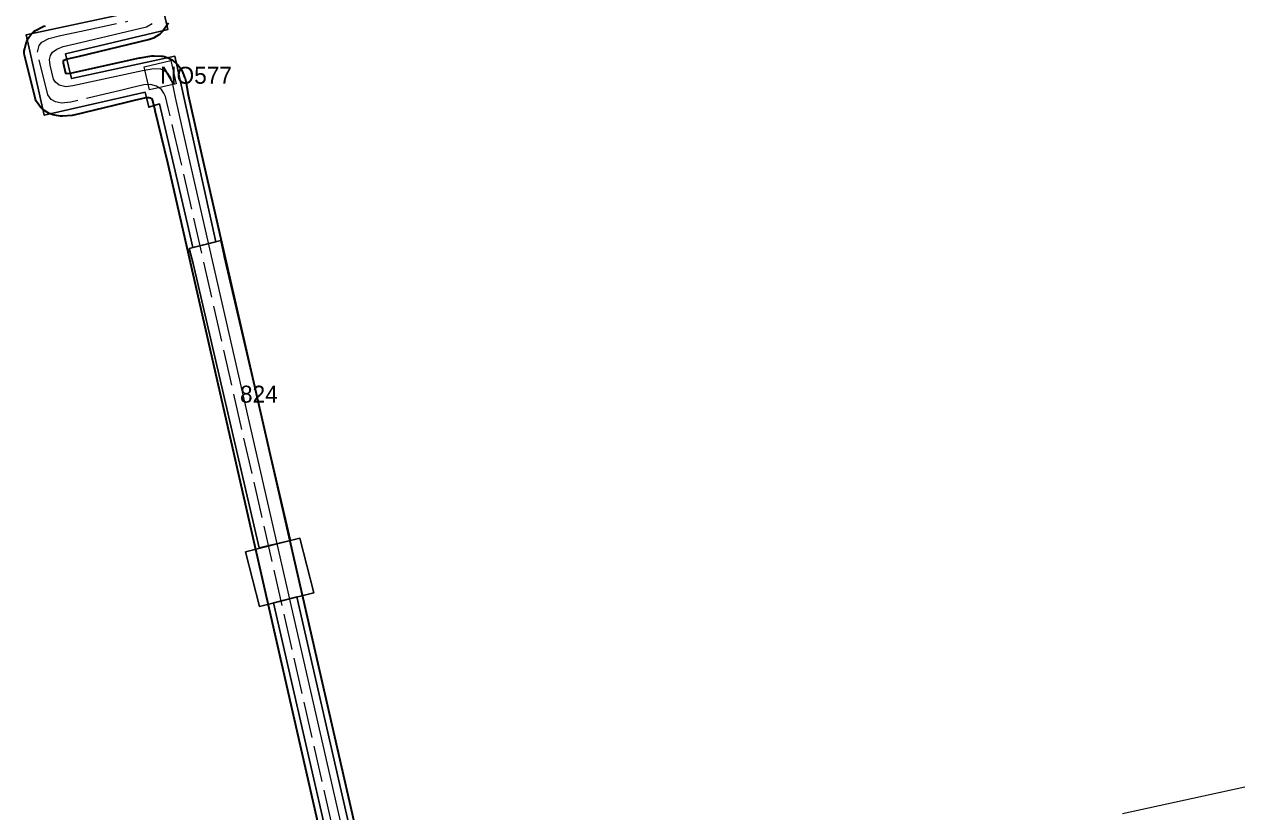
# Model space of a CAD drawing. Extents: x -452602 to -451136, y -1100088 to -1099653.
# Drawn here: x -451913.6 to -451849.1, y -1099899.9 to -1099858.1 of the extents above; entities that cross this region are included whole.
import ezdxf

# ---------------------------------------------------------------- set-up
doc = ezdxf.new("R2010")
doc.units = 0
doc.header["$LTSCALE"] = 0.32
doc.linetypes.add('LONG_DASHED', pattern=[7.5, 6, -1.5])
for name, color, linetype, lineweight in [('2', 7, 'Continuous', 13), ('3', 7, 'Continuous', 25), ('8', 7, 'Continuous', 35)]:
    doc.layers.add(name, color=color, linetype=linetype, lineweight=lineweight)

msp = doc.modelspace()

# ---------------------------------------------------------------- linework, layer by layer
at = {"layer": '2', "linetype": 'LONG_DASHED'}
msp.add_lwpolyline([(-451891.909, -1099924.065), (-451905.286, -1099865.27), (-451905.955, -1099862.503), (-451906.093, -1099861.898), (-451906.173, -1099861.735), (-451906.302, -1099861.528), (-451906.577, -1099861.355), (-451906.884, -1099861.266), (-451907.238, -1099861.285), (-451907.915, -1099861.447), (-451908.42, -1099861.568), (-451911.12, -1099862.214), (-451911.627, -1099862.26), (-451911.931, -1099862.192), (-451912.175, -1099862.058), (-451912.349, -1099861.82), (-451912.903, -1099859.55), (-451912.802, -1099859.197), (-451912.668, -1099859.018), (-451912.301, -1099858.822), (-451911.677, -1099858.668), (-451910.569, -1099858.433), (-451908.098, -1099857.907)], dxfattribs=at)
at = {"layer": '2'}
for points in [[(-451891.367, -1099924.177), (-451904.853, -1099865.12), (-451905.568, -1099861.952), (-451905.66, -1099861.434), (-451905.716, -1099861.175), (-451905.824, -1099860.887), (-451905.946, -1099860.708), (-451906.189, -1099860.519), (-451906.336, -1099860.457), (-451906.717, -1099860.444), (-451907.321, -1099860.54), (-451911.018, -1099861.348), (-451911.384, -1099861.399), (-451911.753, -1099861.303), (-451911.935, -1099861.147), (-451912.05, -1099860.978), (-451912.219, -1099860.243), (-451912.252, -1099859.944), (-451912.204, -1099859.735), (-451912.105, -1099859.541), (-451911.866, -1099859.393), (-451911.527, -1099859.251), (-451910.918, -1099859.111), (-451907.097, -1099858.2), (-451906.807, -1099858.025)], [(-451855.216, -1099900.028), (-451818.069, -1099891.931), (-451811.719, -1099923.681)]]:
    msp.add_lwpolyline(points, dxfattribs=at)
at = {"layer": '3'}
for points in [[(-451904.636, -1099869.929), (-451904.863, -1099868.93), (-451906.412, -1099862.297), (-451906.981, -1099862.474), (-451907.181, -1099861.682), (-451912.537, -1099862.903), (-451913.505, -1099858.632), (-451907.928, -1099857.445), (-451908.108, -1099856.664), (-451907.674, -1099856.581), (-451913.014, -1099833.107), (-451905.472, -1099831.523), (-451907.565, -1099814.42), (-451909.516, -1099798.485), (-451910.152, -1099793.59), (-451908.893, -1099793.361), (-451907.732, -1099803.104), (-451904.112, -1099832.473), (-451911.54, -1099834.039), (-451905.974, -1099858.353), (-451911.404, -1099859.633), (-451911.089, -1099860.954), (-451905.594, -1099859.769), (-451903.412, -1099869.624)], [(-451899.453, -1099885.51), (-451901.105, -1099885.892), (-451904.619, -1099870.784), (-451904.827, -1099869.979), (-451903.158, -1099869.561), (-451902.967, -1099870.401), (-451902.965, -1099870.407)], [(-451901.84, -1099886.118), (-451898.944, -1099885.394), (-451898.204, -1099888.291), (-451901.1, -1099889.016)], [(-451884.541, -1099958.233), (-451888.102, -1099942.592), (-451889.924, -1099934.589), (-451890.439, -1099934.698), (-451890.615, -1099934.004), (-451896.154, -1099935.38), (-451897.17, -1099931.022), (-451891.416, -1099929.782), (-451891.584, -1099929.042), (-451891.175, -1099928.947), (-451900.352, -1099888.829), (-451899.104, -1099888.498), (-451891.188, -1099923.166), (-451889.365, -1099930.782), (-451895.086, -1099932.109), (-451894.784, -1099933.414), (-451889.116, -1099932.088), (-451888.572, -1099934.622), (-451883.239, -1099957.987)]]:
    msp.add_lwpolyline(points, close=True, dxfattribs=at)
at = {"layer": '3', "lineweight": 13}
msp.add_lwpolyline([(-451907.223, -1099860.329), (-451905.807, -1099859.997), (-451905.532, -1099861.232), (-451906.934, -1099861.56)], close=True, dxfattribs=at)
at = {"layer": '8'}
for points in [[(-451892.591, -1099924.223), (-451905.967, -1099865.43), (-451906.635, -1099862.667), (-451906.637, -1099862.659), (-451906.757, -1099862.133), (-451906.786, -1099862.075), (-451906.811, -1099862.034), (-451906.866, -1099862), (-451906.964, -1099861.971), (-451907.137, -1099861.981), (-451907.752, -1099862.128), (-451908.258, -1099862.249), (-451910.957, -1099862.894), (-451910.99, -1099862.901), (-451911.056, -1099862.911), (-451911.564, -1099862.957), (-451911.672, -1099862.958), (-451911.78, -1099862.943), (-451912.083, -1099862.875), (-451912.178, -1099862.847), (-451912.268, -1099862.806), (-451912.513, -1099862.671), (-451912.599, -1099862.616), (-451912.675, -1099862.548), (-451912.742, -1099862.469), (-451912.915, -1099862.231), (-451912.964, -1099862.154), (-451913.002, -1099862.072), (-451913.029, -1099861.986), (-451913.583, -1099859.716), (-451913.601, -1099859.597), (-451913.599, -1099859.477), (-451913.576, -1099859.358), (-451913.475, -1099859.005), (-451913.447, -1099858.925), (-451913.409, -1099858.849), (-451913.363, -1099858.778), (-451913.229, -1099858.599), (-451913.162, -1099858.521), (-451913.084, -1099858.455), (-451912.997, -1099858.4), (-451912.63, -1099858.204), (-451912.552, -1099858.169), (-451912.469, -1099858.143)], [(-451905.946, -1099857.983), (-451905.984, -1099858.069), (-451906.034, -1099858.15), (-451906.238, -1099858.433), (-451906.299, -1099858.506), (-451906.368, -1099858.57), (-451906.446, -1099858.624), (-451906.736, -1099858.8), (-451906.833, -1099858.848), (-451906.935, -1099858.881), (-451910.756, -1099859.792), (-451910.761, -1099859.793), (-451911.312, -1099859.92), (-451911.54, -1099860.016), (-451911.528, -1099860.125), (-451911.402, -1099860.671), (-451911.343, -1099860.687), (-451911.141, -1099860.658), (-451907.47, -1099859.856), (-451907.431, -1099859.849), (-451906.827, -1099859.753), (-451906.76, -1099859.745), (-451906.693, -1099859.744), (-451906.311, -1099859.758), (-451906.227, -1099859.766), (-451906.144, -1099859.784), (-451906.064, -1099859.812), (-451905.917, -1099859.874), (-451905.835, -1099859.915), (-451905.76, -1099859.966), (-451905.516, -1099860.155), (-451905.435, -1099860.229), (-451905.367, -1099860.315), (-451905.245, -1099860.494), (-451905.203, -1099860.565), (-451905.169, -1099860.64), (-451905.061, -1099860.928), (-451905.051, -1099860.955), (-451905.031, -1099861.028), (-451904.976, -1099861.288), (-451904.971, -1099861.312), (-451904.882, -1099861.814), (-451904.17, -1099864.964), (-451890.687, -1099924.013)]]:
    msp.add_lwpolyline(points, dxfattribs=at)

# ---------------------------------------------------------------- texts
at = {"layer": '3'}
for s, p in [('NO577 ', (-451906.374, -1099861.228)), ('824 ', (-451902.132, -1099878.181))]:
    msp.add_text(s, height=0.9, dxfattribs=at).set_placement(p)

doc.saveas('drawing.dxf')
